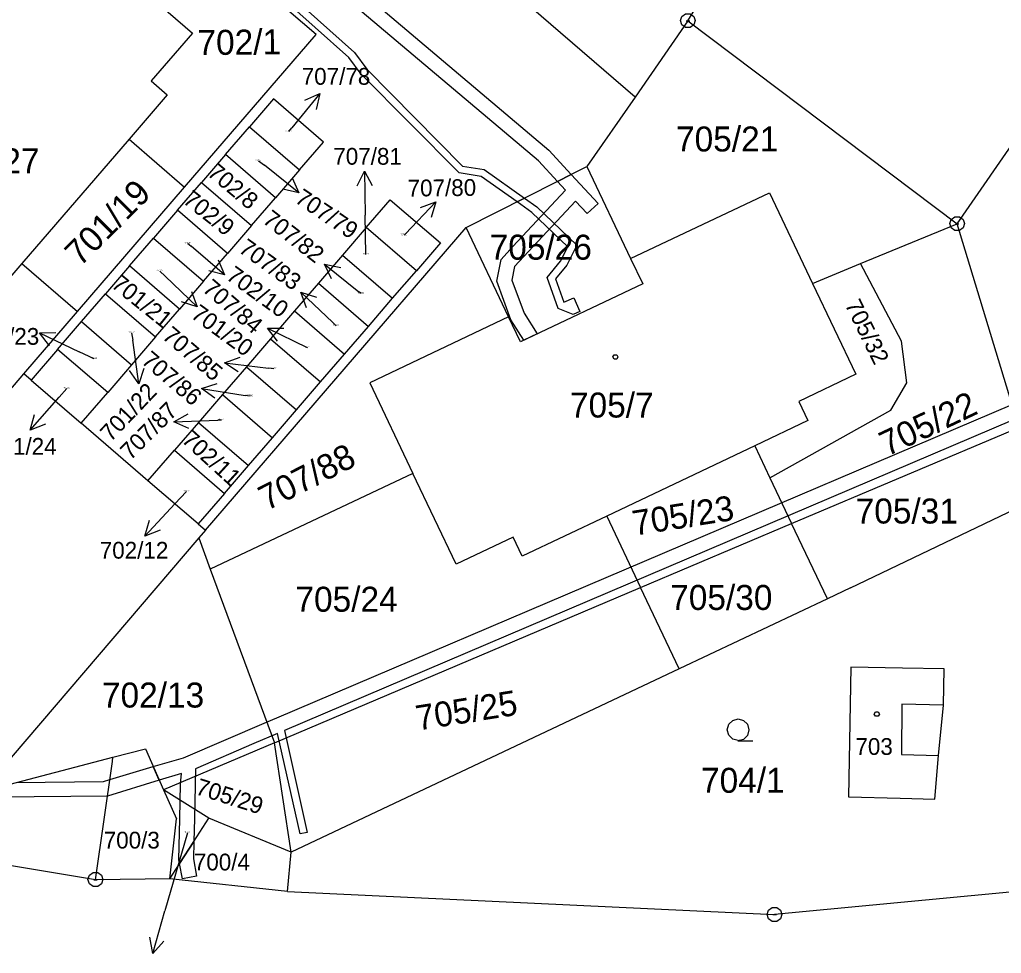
# Model space of a CAD drawing. Extents: x -759060 to -757386, y -1172273 to -1170948.
# Drawn here: x -757823.7 to -757756.9, y -1171173.7 to -1171110.1 of the extents above; entities that cross this region are included whole.
import ezdxf

# ---------------------------------------------------------------- set-up
doc = ezdxf.new("R2010")
doc.units = 0
for name, color, linetype in [('Vrstva 1', 7, 'Continuous'), ('Vrstva 12', 7, 'Continuous'), ('Vrstva 13', 7, 'Continuous'), ('Vrstva 2', 7, 'Continuous'), ('Vrstva 3', 7, 'Continuous'), ('Vrstva 4', 7, 'Continuous'), ('Vrstva 5', 7, 'Continuous'), ('Vrstva 7', 7, 'Continuous'), ('Vrstva 8', 7, 'Continuous')]:
    doc.layers.add(name, color=color, linetype=linetype)

msp = doc.modelspace()

# ---------------------------------------------------------------- linework, layer by layer
at = {"layer": 'Vrstva 1'}
for p, q in [((-757781.84, -1171115.41), (-757802.69, -1171097.45)), ((-757803.54, -1171111.16), (-757813.62, -1171102.48)), ((-757778.25, -1171110.22), (-757774.48, -1171103.94)), ((-757817.15, -1171106.57), (-757811.96, -1171111.05)), ((-757778.25, -1171110.22), (-757781.84, -1171115.41)), ((-757778.25, -1171110.22), (-757759.94, -1171124.03)), ((-757811.96, -1171111.05), (-757814.77, -1171114.3)), ((-757812.49, -1171121.54), (-757803.54, -1171111.16)), ((-757759.94, -1171124.03), (-757751.2, -1171111.37)), ((-757814.77, -1171114.3), (-757813.67, -1171115.26)), ((-757813.67, -1171115.26), (-757816.27, -1171118.28)), ((-757806.45, -1171115.53), (-757808.08, -1171117.43)), ((-757803.04, -1171118.47), (-757806.45, -1171115.53)), ((-757781.84, -1171115.41), (-757785.12, -1171120.14)), ((-757809.71, -1171119.31), (-757808.08, -1171117.43)), ((-757808.08, -1171117.43), (-757804.67, -1171120.36)), ((-757816.27, -1171118.28), (-757823.56, -1171126.73)), ((-757816.27, -1171118.28), (-757812.49, -1171121.54)), ((-757804.67, -1171120.36), (-757803.04, -1171118.47)), ((-757809.71, -1171119.31), (-757811.35, -1171121.21)), ((-757806.3, -1171122.26), (-757809.71, -1171119.31)), ((-757804.67, -1171120.36), (-757806.3, -1171122.26)), ((-757793.33, -1171124.29), (-757785.12, -1171120.14)), ((-757785.12, -1171120.14), (-757782.15, -1171126.4)), ((-757819.77, -1171129.99), (-757812.49, -1171121.54)), ((-757812.97, -1171123.1), (-757811.35, -1171121.21)), ((-757811.35, -1171121.21), (-757807.93, -1171124.15)), ((-757807.93, -1171124.15), (-757806.3, -1171122.26)), ((-757782.15, -1171126.4), (-757772.71, -1171121.92)), ((-757772.71, -1171121.92), (-757769.78, -1171128.08)), ((-757800.13, -1171124.28), (-757798.5, -1171122.39)), ((-757798.5, -1171122.39), (-757795.08, -1171125.32)), ((-757812.97, -1171123.1), (-757814.61, -1171125)), ((-757809.57, -1171126.04), (-757812.97, -1171123.1)), ((-757811.07, -1171144.88), (-757793.33, -1171124.29)), ((-757807.93, -1171124.15), (-757809.57, -1171126.04)), ((-757800.13, -1171124.28), (-757801.76, -1171126.17)), ((-757796.72, -1171127.22), (-757800.13, -1171124.28)), ((-757790.45, -1171130.35), (-757793.33, -1171124.29)), ((-757766.52, -1171126.74), (-757759.94, -1171124.03)), ((-757755.89, -1171137.38), (-757759.94, -1171124.03)), ((-757816.24, -1171126.9), (-757814.61, -1171125)), ((-757814.61, -1171125), (-757811.2, -1171127.94)), ((-757795.08, -1171125.32), (-757796.72, -1171127.22)), ((-757811.2, -1171127.94), (-757809.57, -1171126.04)), ((-757801.76, -1171126.17), (-757803.39, -1171128.06)), ((-757801.76, -1171126.17), (-757798.35, -1171129.1)), ((-757823.56, -1171126.73), (-757827.7, -1171131.54)), ((-757823.56, -1171126.73), (-757819.77, -1171129.99)), ((-757816.24, -1171126.9), (-757817.87, -1171128.79)), ((-757812.83, -1171129.83), (-757816.24, -1171126.9)), ((-757782.15, -1171126.4), (-757781.33, -1171128.11)), ((-757769.78, -1171128.08), (-757766.52, -1171126.74)), ((-757763.73, -1171132.02), (-757766.52, -1171126.74)), ((-757798.35, -1171129.1), (-757796.72, -1171127.22)), ((-757811.2, -1171127.94), (-757812.83, -1171129.83)), ((-757803.39, -1171128.06), (-757805.02, -1171129.96)), ((-757803.39, -1171128.06), (-757799.98, -1171131.01)), ((-757781.33, -1171128.11), (-757789.64, -1171132.06)), ((-757769.78, -1171128.08), (-757766.84, -1171134.27)), ((-757819.5, -1171130.68), (-757817.87, -1171128.79)), ((-757817.87, -1171128.79), (-757814.46, -1171131.73)), ((-757799.98, -1171131.01), (-757798.35, -1171129.1)), ((-757823.42, -1171134.24), (-757819.77, -1171129.99)), ((-757814.46, -1171131.73), (-757812.83, -1171129.83)), ((-757805.02, -1171129.96), (-757806.65, -1171131.85)), ((-757805.02, -1171129.96), (-757801.61, -1171132.89)), ((-757790.45, -1171130.35), (-757799.89, -1171134.84)), ((-757789.64, -1171132.06), (-757790.45, -1171130.35)), ((-757821.13, -1171132.57), (-757819.5, -1171130.68)), ((-757819.5, -1171130.68), (-757816.09, -1171133.62)), ((-757801.61, -1171132.89), (-757799.98, -1171131.01)), ((-757814.46, -1171131.73), (-757816.09, -1171133.62)), ((-757806.65, -1171131.85), (-757808.29, -1171133.75)), ((-757806.65, -1171131.85), (-757803.24, -1171134.79)), ((-757763.37, -1171134.84), (-757763.73, -1171132.02)), ((-757821.13, -1171132.57), (-757822.93, -1171134.66)), ((-757817.72, -1171135.51), (-757821.13, -1171132.57)), ((-757803.24, -1171134.79), (-757801.61, -1171132.89)), ((-757816.09, -1171133.62), (-757817.72, -1171135.51)), ((-757829.98, -1171141.85), (-757823.42, -1171134.24)), ((-757822.93, -1171134.66), (-757823.42, -1171134.24)), ((-757808.29, -1171133.75), (-757809.91, -1171135.64)), ((-757808.29, -1171133.75), (-757804.87, -1171136.68)), ((-757766.84, -1171134.27), (-757770.72, -1171136.11)), ((-757822.93, -1171134.66), (-757819.52, -1171137.6)), ((-757804.87, -1171136.68), (-757803.24, -1171134.79)), ((-757799.89, -1171134.84), (-757796.96, -1171141.01)), ((-757764.46, -1171136.7), (-757763.37, -1171134.84)), ((-757819.52, -1171137.6), (-757817.72, -1171135.51)), ((-757809.91, -1171135.64), (-757811.55, -1171137.54)), ((-757809.91, -1171135.64), (-757806.51, -1171138.58)), ((-757770.72, -1171136.11), (-757770.1, -1171137.42)), ((-757806.51, -1171138.58), (-757804.87, -1171136.68)), ((-757772.68, -1171141.31), (-757764.46, -1171136.7)), ((-757814.98, -1171141.52), (-757819.52, -1171137.6)), ((-757811.55, -1171137.54), (-757813.18, -1171139.43)), ((-757811.55, -1171137.54), (-757808.14, -1171140.47)), ((-757770.1, -1171137.42), (-757773.71, -1171139.14)), ((-757771.2, -1171144.42), (-757755.74, -1171137.88)), ((-757808.14, -1171140.47), (-757806.51, -1171138.58)), ((-757814.98, -1171141.52), (-757813.18, -1171139.43)), ((-757813.18, -1171139.43), (-757809.77, -1171142.37)), ((-757773.71, -1171139.14), (-757783.78, -1171143.93)), ((-757773.71, -1171139.14), (-757772.68, -1171141.31)), ((-757796.96, -1171141.01), (-757810.74, -1171147.52)), ((-757809.77, -1171142.37), (-757808.14, -1171140.47)), ((-757794.02, -1171147.18), (-757796.96, -1171141.01)), ((-757811.57, -1171144.45), (-757814.98, -1171141.52)), ((-757772.68, -1171141.31), (-757771.2, -1171144.42)), ((-757809.77, -1171142.37), (-757811.57, -1171144.45)), ((-757767.2, -1171148.8), (-757755, -1171142.95)), ((-757783.78, -1171143.93), (-757789.52, -1171146.65)), ((-757783.78, -1171143.93), (-757781.48, -1171148.77)), ((-757811.57, -1171144.45), (-757811.07, -1171144.88)), ((-757811.07, -1171144.88), (-757811.53, -1171145.4)), ((-757781.48, -1171148.77), (-757771.2, -1171144.42)), ((-757768.77, -1171149.54), (-757771.2, -1171144.42)), ((-757811.53, -1171145.4), (-757826.26, -1171162.64)), ((-757811.53, -1171145.4), (-757810.74, -1171147.52)), ((-757790.14, -1171145.34), (-757794.02, -1171147.18)), ((-757789.52, -1171146.65), (-757790.14, -1171145.34)), ((-757810.74, -1171147.52), (-757806.38, -1171159.33)), ((-757806.38, -1171159.33), (-757781.48, -1171148.77)), ((-757778.85, -1171154.3), (-757781.48, -1171148.77)), ((-757767.2, -1171148.8), (-757768.77, -1171149.54)), ((-757768.77, -1171149.54), (-757778.85, -1171154.3)), ((-757778.85, -1171154.3), (-757805.23, -1171166.77)), ((-757767.18, -1171154.19), (-757767.34, -1171163.01)), ((-757763.66, -1171154.26), (-757767.18, -1171154.19)), ((-757760.83, -1171154.31), (-757763.66, -1171154.26)), ((-757760.88, -1171156.77), (-757760.83, -1171154.31)), ((-757761.21, -1171160.21), (-757760.88, -1171156.77)), ((-757817.36, -1171160.32), (-757815.16, -1171159.75)), ((-757815.16, -1171159.75), (-757813.92, -1171162.53)), ((-757806.38, -1171159.33), (-757813.92, -1171162.53)), ((-757805.23, -1171166.77), (-757806.38, -1171159.33)), ((-757826.26, -1171162.64), (-757817.36, -1171160.32)), ((-757817.4, -1171160.6), (-757817.36, -1171160.32)), ((-757761.47, -1171163.17), (-757761.21, -1171160.21)), ((-757818.55, -1171168.65), (-757817.4, -1171160.6)), ((-757818.55, -1171168.65), (-757857.63, -1171162.23)), ((-757810.84, -1171164.47), (-757813.92, -1171162.53)), ((-757813.92, -1171162.53), (-757813.04, -1171164.52)), ((-757767.34, -1171163.01), (-757763.81, -1171163.11)), ((-757763.81, -1171163.11), (-757761.47, -1171163.17)), ((-757813.5, -1171168.6), (-757810.84, -1171164.47)), ((-757813.5, -1171168.6), (-757813.04, -1171164.52)), ((-757805.23, -1171166.77), (-757810.84, -1171164.47)), ((-757805.5, -1171169.45), (-757805.23, -1171166.77)), ((-757813.5, -1171168.6), (-757818.55, -1171168.65)), ((-757805.5, -1171169.45), (-757813.5, -1171168.6)), ((-757747.08, -1171168.6), (-757772.36, -1171171.03)), ((-757805.5, -1171169.45), (-757772.36, -1171171.03))]:
    msp.add_line(p, q, dxfattribs=at)
at = {"layer": 'Vrstva 12'}
for p, q in [((-757817.15, -1171106.57), (-757811.96, -1171111.05)), ((-757811.96, -1171111.05), (-757814.77, -1171114.3)), ((-757814.77, -1171114.3), (-757813.67, -1171115.26)), ((-757813.67, -1171115.26), (-757816.27, -1171118.28)), ((-757816.27, -1171118.28), (-757823.56, -1171126.73)), ((-757782.15, -1171126.4), (-757772.71, -1171121.92)), ((-757772.71, -1171121.92), (-757769.78, -1171128.08)), ((-757823.56, -1171126.73), (-757827.7, -1171131.54)), ((-757782.15, -1171126.4), (-757781.33, -1171128.11)), ((-757781.33, -1171128.11), (-757789.64, -1171132.06)), ((-757769.78, -1171128.08), (-757766.84, -1171134.27)), ((-757790.45, -1171130.35), (-757799.89, -1171134.84)), ((-757789.64, -1171132.06), (-757790.45, -1171130.35)), ((-757766.84, -1171134.27), (-757770.72, -1171136.11)), ((-757799.89, -1171134.84), (-757796.96, -1171141.01)), ((-757770.72, -1171136.11), (-757770.1, -1171137.42)), ((-757770.1, -1171137.42), (-757773.71, -1171139.14)), ((-757773.71, -1171139.14), (-757783.78, -1171143.93)), ((-757794.02, -1171147.18), (-757796.96, -1171141.01)), ((-757783.78, -1171143.93), (-757789.52, -1171146.65)), ((-757790.14, -1171145.34), (-757794.02, -1171147.18)), ((-757789.52, -1171146.65), (-757790.14, -1171145.34)), ((-757767.18, -1171154.19), (-757767.34, -1171163.01)), ((-757763.66, -1171154.26), (-757767.18, -1171154.19)), ((-757760.83, -1171154.31), (-757763.66, -1171154.26)), ((-757760.88, -1171156.77), (-757760.83, -1171154.31)), ((-757763.71, -1171156.72), (-757763.73, -1171160.14)), ((-757760.88, -1171156.77), (-757763.71, -1171156.72)), ((-757763.73, -1171160.14), (-757761.21, -1171160.21)), ((-757761.47, -1171163.17), (-757761.21, -1171160.21)), ((-757767.34, -1171163.01), (-757763.81, -1171163.11)), ((-757763.81, -1171163.11), (-757761.47, -1171163.17))]:
    msp.add_line(p, q, dxfattribs=at)
at = {"layer": 'Vrstva 13'}
for p, q in [((-757822.78, -1171089.36), (-757787.72, -1171119.02)), ((-757788.42, -1171119.74), (-757823.44, -1171090.12)), ((-757801.32, -1171112.72), (-757819.11, -1171096.77)), ((-757818.76, -1171096.41), (-757800.94, -1171112.38)), ((-757800.48, -1171113.84), (-757801.32, -1171112.72)), ((-757800.94, -1171112.38), (-757800.1, -1171113.52)), ((-757800.1, -1171113.52), (-757793.58, -1171120.1)), ((-757793.82, -1171120.56), (-757800.48, -1171113.84)), ((-757787.72, -1171119.02), (-757786.19, -1171120.68)), ((-757793.58, -1171120.1), (-757792.11, -1171120.34)), ((-757792.11, -1171120.34), (-757789.37, -1171122.29)), ((-757787.12, -1171121.15), (-757788.42, -1171119.74)), ((-757792.31, -1171120.82), (-757793.82, -1171120.56)), ((-757789.87, -1171122.54), (-757792.31, -1171120.82)), ((-757786.19, -1171120.68), (-757787.12, -1171121.15)), ((-757787.12, -1171121.15), (-757786.19, -1171120.68)), ((-757786.19, -1171120.68), (-757784.37, -1171122.66)), ((-757786.57, -1171121.74), (-757787.12, -1171121.15)), ((-757790.16, -1171125.58), (-757786.57, -1171121.74)), ((-757789.37, -1171122.29), (-757789.87, -1171122.54)), ((-757789.87, -1171122.54), (-757789.37, -1171122.29)), ((-757789.37, -1171122.29), (-757788.54, -1171122.88)), ((-757788.86, -1171123.26), (-757789.87, -1171122.54)), ((-757785.9, -1171122.49), (-757789.42, -1171126.26)), ((-757788.54, -1171122.88), (-757785.81, -1171125.49)), ((-757785.11, -1171123.34), (-757785.9, -1171122.49)), ((-757784.37, -1171122.66), (-757785.11, -1171123.34)), ((-757786.43, -1171125.59), (-757788.86, -1171123.26)), ((-757790.96, -1171126.45), (-757790.16, -1171125.58)), ((-757786.92, -1171126.57), (-757786.43, -1171125.59)), ((-757785.81, -1171125.49), (-757786.5, -1171126.85)), ((-757789.42, -1171126.26), (-757790.04, -1171126.93)), ((-757791.26, -1171127.94), (-757790.96, -1171126.45)), ((-757790.04, -1171126.93), (-757790.22, -1171127.86)), ((-757787.83, -1171127.68), (-757786.92, -1171126.57)), ((-757786.5, -1171126.85), (-757787.27, -1171127.78)), ((-757787.08, -1171129.8), (-757787.83, -1171127.68)), ((-757790.29, -1171130.56), (-757791.26, -1171127.94)), ((-757790.22, -1171127.86), (-757789.39, -1171130.12)), ((-757787.27, -1171127.78), (-757786.7, -1171129.37)), ((-757786.7, -1171129.37), (-757786.01, -1171129.07)), ((-757786.01, -1171129.07), (-757785.61, -1171129.99)), ((-757789.39, -1171130.12), (-757788.5, -1171131.52)), ((-757786.07, -1171130.19), (-757787.08, -1171129.8)), ((-757785.61, -1171129.99), (-757786.07, -1171130.19)), ((-757789.41, -1171131.95), (-757790.29, -1171130.56)), ((-757788.5, -1171131.52), (-757789.41, -1171131.95)), ((-757806.22, -1171157.63), (-757756.21, -1171136.32)), ((-757756.23, -1171137.41), (-757805.7, -1171158.49)), ((-757806.91, -1171157.93), (-757806.22, -1171157.63)), ((-757812.56, -1171160.35), (-757806.91, -1171157.93)), ((-757806.18, -1171158.7), (-757807.79, -1171159.39)), ((-757804.63, -1171165.54), (-757806.18, -1171158.7)), ((-757805.7, -1171158.49), (-757804.15, -1171165.43)), ((-757807.79, -1171159.39), (-757811.75, -1171161.1)), ((-757814.62, -1171160.96), (-757812.56, -1171160.35)), ((-757817.58, -1171161.84), (-757814.62, -1171160.96)), ((-757814.21, -1171161.88), (-757814.62, -1171160.96)), ((-757814.62, -1171160.96), (-757814.21, -1171161.88)), ((-757812.69, -1171161.42), (-757814.21, -1171161.88)), ((-757812.77, -1171162.12), (-757812.69, -1171161.42)), ((-757811.75, -1171161.1), (-757811.82, -1171164.49)), ((-757823.94, -1171162.04), (-757818.01, -1171161.97)), ((-757818.01, -1171161.97), (-757817.58, -1171161.84)), ((-757814.21, -1171161.88), (-757817.74, -1171162.96)), ((-757812.82, -1171164.52), (-757812.77, -1171162.12)), ((-757817.74, -1171162.96), (-757830.6, -1171163.11)), ((-757812.88, -1171167.31), (-757812.82, -1171164.52)), ((-757811.82, -1171164.49), (-757811.85, -1171166.05)), ((-757804.15, -1171165.43), (-757804.63, -1171165.54)), ((-757812.83, -1171167.56), (-757811.85, -1171166.05)), ((-757811.85, -1171166.05), (-757812.83, -1171167.56)), ((-757811.85, -1171166.05), (-757811.88, -1171167.23)), ((-757812.83, -1171167.56), (-757812.88, -1171167.31)), ((-757812.63, -1171168.59), (-757812.83, -1171167.56)), ((-757811.88, -1171167.23), (-757811.67, -1171168.41)), ((-757811.67, -1171168.41), (-757812.63, -1171168.59))]:
    msp.add_line(p, q, dxfattribs=at)
at = {"layer": 'Vrstva 3'}
msp.add_lwpolyline([(-757774.83, -1171159.19), (-757775.21, -1171159.09), (-757775.48, -1171158.82), (-757775.58, -1171158.45), (-757775.48, -1171158.08), (-757775.21, -1171157.81), (-757774.84, -1171157.71), (-757774.47, -1171157.81), (-757774.2, -1171158.08), (-757774.1, -1171158.46), (-757774.2, -1171158.84), (-757774.47, -1171159.11), (-757774.85, -1171159.21), (-757773.85, -1171159.21)], dxfattribs=at)
at = {"layer": 'Vrstva 4'}
for p, q in [((-757763.71, -1171156.72), (-757763.73, -1171160.14)), ((-757760.88, -1171156.77), (-757763.71, -1171156.72)), ((-757763.73, -1171160.14), (-757761.21, -1171160.21))]:
    msp.add_line(p, q, dxfattribs=at)
at = {"layer": 'Vrstva 5'}
for points in [[(-757783.1, -1171132.94), (-757783.01, -1171133.09), (-757783.1, -1171133.24), (-757783.28, -1171133.24), (-757783.37, -1171133.09), (-757783.28, -1171132.94)], [(-757765.32, -1171157.23), (-757765.23, -1171157.38), (-757765.32, -1171157.53), (-757765.5, -1171157.53), (-757765.59, -1171157.38), (-757765.5, -1171157.23)]]:
    msp.add_lwpolyline(points, close=True, dxfattribs=at)
at = {"layer": 'Vrstva 7'}
for p, q in [((-757803.301, -1171115.16), (-757805.19, -1171117.49)), ((-757805.4, -1171117.74), (-757805.19, -1171117.49)), ((-757807.46, -1171119.74), (-757807.06, -1171120.05)), ((-757804.709, -1171121.914), (-757807.06, -1171120.05)), ((-757800.258, -1171120.44), (-757800.21, -1171123.44)), ((-757795.402, -1171122.538), (-757797.46, -1171124.72)), ((-757800.17, -1171126.11), (-757800.21, -1171123.44)), ((-757797.55, -1171124.81), (-757797.46, -1171124.72)), ((-757812.26, -1171125.37), (-757812.04, -1171125.55)), ((-757809.766, -1171127.506), (-757812.04, -1171125.55)), ((-757802.965, -1171126.766), (-757800.63, -1171128.65)), ((-757814.18, -1171127.25), (-757813.8, -1171127.6)), ((-757811.641, -1171129.683), (-757813.8, -1171127.6)), ((-757804.579, -1171128.688), (-757802.4, -1171130.75)), ((-757800.48, -1171128.78), (-757800.63, -1171128.65)), ((-757802.18, -1171130.96), (-757802.4, -1171130.75)), ((-757822.359, -1171131.442), (-757819.65, -1171132.73)), ((-757816.1, -1171131.44), (-757816.02, -1171131.95)), ((-757806.848, -1171131.138), (-757804.15, -1171132.45)), ((-757815.612, -1171134.922), (-757816.02, -1171131.95)), ((-757818.64, -1171133.22), (-757819.65, -1171132.73)), ((-757804.14, -1171132.46), (-757804.15, -1171132.45)), ((-757809.769, -1171133.484), (-757806.79, -1171133.84)), ((-757806.41, -1171133.89), (-757806.79, -1171133.84)), ((-757820.5, -1171135.24), (-757821.01, -1171135.82)), ((-757811.344, -1171135.234), (-757808.38, -1171135.7)), ((-757808.03, -1171135.76), (-757808.38, -1171135.7)), ((-757822.987, -1171138.076), (-757821.01, -1171135.82)), ((-757813.218, -1171137.501), (-757810.22, -1171137.38)), ((-757809.99, -1171137.38), (-757810.22, -1171137.38)), ((-757812.36, -1171142.24), (-757813.15, -1171143.08)), ((-757815.198, -1171145.272), (-757813.15, -1171143.08)), ((-757812.29, -1171165.46), (-757813.83, -1171170.78)), ((-757814.661, -1171173.663), (-757813.83, -1171170.78))]:
    msp.add_line(p, q, dxfattribs=at)
for points in [[(-757804.319, -1171115.621), (-757803.301, -1171115.16), (-757803.542, -1171116.251)], [(-757805.182, -1171120.901), (-757804.709, -1171121.914), (-757805.803, -1171121.684)], [(-757800.742, -1171121.448), (-757800.258, -1171120.44), (-757799.742, -1171121.432)], [(-757796.451, -1171122.922), (-757795.402, -1171122.538), (-757795.724, -1171123.608)], [(-757810.198, -1171126.475), (-757809.766, -1171127.506), (-757810.85, -1171127.233)], [(-757802.501, -1171127.783), (-757802.965, -1171126.766), (-757801.873, -1171127.005)], [(-757812.013, -1171128.629), (-757811.641, -1171129.683), (-757812.708, -1171129.348)], [(-757804.196, -1171129.739), (-757804.579, -1171128.688), (-757803.509, -1171129.012)], [(-757821.671, -1171132.323), (-757822.359, -1171131.442), (-757821.242, -1171131.42)], [(-757806.167, -1171132.025), (-757806.848, -1171131.138), (-757805.73, -1171131.125)], [(-757808.835, -1171134.099), (-757809.769, -1171133.484), (-757808.717, -1171133.106)], [(-757815.253, -1171133.863), (-757815.612, -1171134.922), (-757816.243, -1171133.999)], [(-757810.433, -1171135.884), (-757811.344, -1171135.234), (-757810.278, -1171134.896)], [(-757821.952, -1171137.654), (-757822.987, -1171138.076), (-757822.704, -1171136.995)], [(-757812.198, -1171137.96), (-757813.218, -1171137.501), (-757812.238, -1171136.961)], [(-757814.15, -1171144.883), (-757815.198, -1171145.272), (-757814.881, -1171144.2)], [(-757813.903, -1171172.84), (-757814.661, -1171173.663), (-757814.864, -1171172.563)]]:
    msp.add_lwpolyline(points, dxfattribs=at)
at = {"layer": 'Vrstva 8'}
for p, q in [((-757778.37, -1171110.22), (-757778.13, -1171110.22)), ((-757760.06, -1171124.03), (-757759.82, -1171124.03)), ((-757818.67, -1171168.65), (-757818.43, -1171168.65)), ((-757772.48, -1171171.03), (-757772.24, -1171171.03))]:
    msp.add_line(p, q, dxfattribs=at)
for points in [[(-757778.1, -1171109.74), (-757777.85, -1171109.92), (-757777.75, -1171110.21), (-757777.85, -1171110.5), (-757778.1, -1171110.68), (-757778.41, -1171110.68), (-757778.66, -1171110.5), (-757778.76, -1171110.21), (-757778.66, -1171109.92), (-757778.41, -1171109.74)], [(-757759.79, -1171123.55), (-757759.54, -1171123.73), (-757759.44, -1171124.02), (-757759.54, -1171124.31), (-757759.79, -1171124.49), (-757760.1, -1171124.49), (-757760.35, -1171124.31), (-757760.45, -1171124.02), (-757760.35, -1171123.73), (-757760.1, -1171123.55)], [(-757818.4, -1171168.17), (-757818.15, -1171168.35), (-757818.05, -1171168.64), (-757818.15, -1171168.93), (-757818.4, -1171169.11), (-757818.71, -1171169.11), (-757818.96, -1171168.93), (-757819.06, -1171168.64), (-757818.96, -1171168.35), (-757818.71, -1171168.17)], [(-757772.21, -1171170.55), (-757771.96, -1171170.73), (-757771.86, -1171171.02), (-757771.96, -1171171.31), (-757772.21, -1171171.49), (-757772.52, -1171171.49), (-757772.77, -1171171.31), (-757772.87, -1171171.02), (-757772.77, -1171170.73), (-757772.52, -1171170.55)]]:
    msp.add_lwpolyline(points, close=True, dxfattribs=at)

# ---------------------------------------------------------------- texts
at = {"layer": 'Vrstva 2'}
for s, height, rotation, p in [('702/1', 1.7, 0.63025, (-757811.605, -1171112.555)), ('702/8', 1.14, 320.16882, (-757811.019, -1171120.681)), ('701/19', 1.7, 44.97719, (-757819.594, -1171126.992)), ('702/9', 1.14, 321.54391, (-757812.674, -1171122.553)), ('701/21', 1.14, 321.20014, (-757817.552, -1171128.285)), ('705/32', 1.14, 296.16188, (-757767.606, -1171129.522)), ('705/22', 1.7, 25.26744, (-757764.712, -1171139.877)), ('702/11', 1.14, 317.59051, (-757812.756, -1171138.823)), ('707/88', 1.7, 26.98631, (-757806.898, -1171143.578)), ('705/23', 1.7, 8.99544, (-757781.894, -1171145.255)), ('705/25', 1.7, 8.99544, (-757796.624, -1171158.509)), ('705/29', 1.14, 342.45688, (-757811.814, -1171162.815))]:
    msp.add_text(s, height=height, rotation=rotation, dxfattribs=at).set_placement(p)
for s, height, p in [('707/78', 0.1, (-757805.638, -1171117.74)), ('705/21', 1.7, (-757779.062, -1171119.11)), ('701/27', 1.7, (-757829.314, -1171120.6)), ('707/79', 0.1, (-757807.697, -1171119.74)), ('707/80', 0.1, (-757797.792, -1171124.81)), ('705/26', 1.7, (-757791.74, -1171126.47)), ('702/10', 0.1, (-757812.487, -1171125.37)), ('707/81', 0.1, (-757800.39, -1171126.11)), ('701/20', 0.1, (-757814.407, -1171127.25)), ('707/82', 0.1, (-757800.725, -1171128.78)), ('707/83', 0.1, (-757802.426, -1171130.96)), ('701/22', 0.1, (-757816.33, -1171131.44)), ('707/84', 0.1, (-757804.381, -1171132.46)), ('701/23', 0.1, (-757818.871, -1171133.22)), ('707/85', 0.1, (-757806.654, -1171133.89)), ('701/24', 0.1, (-757820.726, -1171135.24)), ('707/86', 0.1, (-757808.271, -1171135.76)), ('705/7', 1.7, (-757786.276, -1171137.21)), ('707/87', 0.1, (-757810.229, -1171137.38)), ('702/12', 0.1, (-757812.59, -1171142.24)), ('705/31', 1.7, (-757766.845, -1171144.42)), ('705/24', 1.7, (-757804.95, -1171150.42)), ('705/30', 1.7, (-757779.46, -1171150.3)), ('702/13', 1.7, (-757818.112, -1171156.94)), ('703', 1.14, (-757766.86, -1171160.16)), ('704/1', 1.7, (-757777.362, -1171162.74)), ('700/3', 1.14, (-757817.99, -1171166.53)), ('705/33', 0.1, (-757812.545, -1171165.46)), ('700/4', 1.14, (-757811.861, -1171168.02))]:
    msp.add_text(s, height=height, dxfattribs=at).set_placement(p)
at = {"layer": 'Vrstva 7'}
for s, p in [('707/78', (-757804.522, -1171114.57)), ('707/81', (-757802.374, -1171120.01)), ('701/23', (-757827.037, -1171132.26)), ('701/24', (-757825.856, -1171139.74)), ('702/12', (-757818.259, -1171146.81))]:
    msp.add_text(s, height=1.14, dxfattribs=at).set_placement(p)
for s, rotation, p in [('707/80', 0.63025, (-757797.315, -1171122.177)), ('707/79', 326.12758, (-757805.068, -1171122.519)), ('707/82', 322.11687, (-757807.256, -1171123.904)), ('707/83', 324.35141, (-757808.889, -1171125.896)), ('702/10', 324.00763, (-757809.738, -1171127.745)), ('707/84', 319.48127, (-757811.341, -1171128.565)), ('701/20', 323.83574, (-757812.134, -1171130.36)), ('707/85', 319.71045, (-757814.079, -1171131.784)), ('707/86', 319.71045, (-757815.498, -1171133.462)), ('701/22', 46.35229, (-757817.517, -1171138.914)), ('707/87', 45.14908, (-757816.172, -1171140.161))]:
    msp.add_text(s, height=1.14, rotation=rotation, dxfattribs=at).set_placement(p)

doc.saveas('drawing.dxf')
